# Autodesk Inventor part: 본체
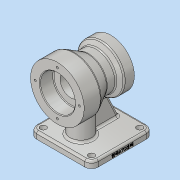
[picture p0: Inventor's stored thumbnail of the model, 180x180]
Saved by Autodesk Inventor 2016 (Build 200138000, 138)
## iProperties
Created: 2019-01
Part Number: 본체
Material: 알루미늄 6061
Document SubType Name: Modeling
Designer: Administrator
Density: 2.7 g/cm^3
Appearance: 알루미늄 - 평지
Mass: 898.816 g
Surface Area: 600.964 cm^2
Volume: 332.895 cm^3
Author: Administrator
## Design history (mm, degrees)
sketch "스케치1"
  geometry: L1 (0, 40)-(25, 40); L2 (25, 40)-(45.785, 28); L3 (45.785, 28)-(59.126, 28); L4 (65, 35)-(80, 35); L5 (80, 35)-(80, 20); L6 (80, 20)-(63, 20); L7 (63, 20)-(63, 16); L8 (63, 16)-(20, 16); L9 (20, 16)-(20, 26); L10 (20, 26)-(0, 26); L11 (0, 26)-(0, 40); L12 (0, 0)-(66.05, 0); L13 (59.126, 28)-(65, 35)
  constraints: 26 end point, 7 perpendicular, 2 horizontal, 2 parallel, 1 vertical alignment
  dimensions: "d0" = 52 diameter of L10 L12; "d1" = 80 diameter of L1 L12; "d2" = 25 distance of L1.start L1.end; "d3" = 80 distance between parallel lines of L5 L11; "d4" = 56 diameter of L3 L12; "d5" = 32 diameter of L8 L12; "d6" = 40 diameter of L6 L12; "d7" = 70 diameter of L4 L12; "d8" = 15 distance of L4.start L4.end; "d9" = 17 distance of L5.end L6.end; "d10" = 20 distance of L9.end L10.end; "d11" = 30 deg angle of L3 L2; "d12" = 50 deg angle of L3 L13
revolve "회전1" sketch "스케치1" stored, may be unused: angle "d13" = 90 deg
node "작업 평면2"
sketch "스케치4"
  geometry: L1 (-46, 5)-(46, 5); L2 (46, 5)-(46, 97); L3 (46, 97)-(-46, 97); L4 (-46, 97)-(-46, 5); L5 (40, 0)-(-40, 0) reference; 3 further points
  constraints: 8 end point, 2 midpoint, 2 parallel, 1 horizontal, 1 perpendicular, 1 vertical alignment
  dimensions: "d19" = 5 distance between parallel lines of L1 L5; "d20" = 92 distance of L1.end L2.end; "d21" = 92 distance of L1.start L1.end
extrude "돌출1" join sketch "스케치4" distance "d22" = 10; taper "d23" = 0 deg
sketch "스케치5"
  geometry: L1 (-46, 5)-(46, 5) reference; L2 (-46, 97)-(-46, 5) reference; C1 r 16 at (0, 35); 1 further point
  constraints: 1 centre point
  dimensions: "d24" = 16 radius of C1; "d25" = 30 distance from line of L1 C1.centre; "d26" = 46 distance from line of C1.centre L2
extrude "돌출2" join sketch "스케치5" stored distance "d27" = 0; taper "d28" = 0 deg
sketch "스케치6"
  geometry: L1 (97, -70)-(5, -70) reference; L2 (87, -70)-(76.94, -48.425); L3 (97, -80)-(97, -70) reference; 1 further point
  constraints: 2 end point, 1 point on line
  dimensions: "d29" = 10 distance of L1.start L2.start; "d30" = 25 deg angle of L3 L2
feature "리브1" sketch "스케치6" dims "d31" = 1, "d32" = 10, "d33" = 0, "d34" = 0, "d35" = 1, "d36" = 1
fillet "모깎기1" dims "d37" = 10
fillet "모깎기2" dims "d38" = 3
sketch "스케치7"
  geometry: L1 (36, 97)-(-36, 97) reference; L2 (46, 15)-(46, 87) reference; L3 (-36, 5)-(36, 5) reference; L4 (-46, 87)-(-46, 15) reference; A1 r 10 centre (-36, 87) between (-36, 97) and (-46, 87) reference; A2 r 10 centre (36, 87) between (46, 87) and (36, 97) reference; A3 r 10 centre (36, 15) between (36, 5) and (46, 15) reference; A4 r 10 centre (-36, 15) between (-46, 15) and (-36, 5) reference; 5 further points
  constraints: 4 coincident
hole "구멍1" sketch "스케치7" at (-36, 87), (36, 87), (36, 15), (-36, 15) diameter "d39" = 9; stored, may be unused: countersink angle "d43" = 90 deg, drill point angle "d45" = 0 deg; dims "d40" = 6, "d41" = 4, "d42" = 2, "d44" = 8
chamfer "모따기1" distance "d46" = 1; stored, may be unused: second distance "d47" = 2, angle "d48" = 45 deg
fillet "모깎기3" dims "d49" = 1
fillet "모깎기4" dims "d50" = 0.6
sketch "스케치8"
  geometry: L1 (0, 0)-(0, 33); 1 further point
  constraints: 2 end point, 1 coincident, 1 vertical
  dimensions: "d51" = 33 distance of L1.start L1.end
hole "구멍2" sketch "스케치8" at (0, 33) diameter "d52" = 3.242; stored, may be unused: countersink angle "d56" = 90 deg, drill point angle "d58" = 118 deg; dims "d53" = 9, "d54" = 4, "d55" = 2, "d57" = 11
sketch "스케치9"
  geometry: L1 (0, 0)-(0, -27.5); 1 further point
  constraints: 2 end point, 1 coincident, 1 vertical
  dimensions: "d62" = 27.5 distance of L1.start L1.end
hole "구멍3" sketch "스케치9" at (0, -27.5) diameter "d63" = 3.242; stored, may be unused: countersink angle "d67" = 90 deg, drill point angle "d69" = 118 deg; dims "d64" = 9, "d65" = 4, "d66" = 2, "d68" = 11
fillet "모깎기5" dims "d73" = 3
fillet "모깎기6" dims "d74" = 3
fillet "모깎기7" dims "d75" = 3
fillet "모깎기8" dims "d76" = 3
sketch "스케치10"
  geometry: L1 (-7, 0)-(-7, 72) reference; L2 (0, 0)-(-7, 0) reference; L3 (0, 0)-(0, 72) reference; L4 (-7, 72)-(0, 72) reference; L5 (-7, -10)-(0, -10) reference; 2 further points
  constraints: 1 other
  dimensions: "d77" = 46 distance from line of L5 point (-4, 36); "d78" = 4 distance from line of L3 point (-4, 36)
feature "엠보싱1" sketch "스케치10" dims "d0" = 52, "d1" = 80, "d2" = 25, "d3" = 80, "d4" = 56, "d5" = 32, "d6" = 40, "d7" = 70, "d8" = 15, "d9" = 17, "d10" = 20, "d11" = 30 deg, "d12" = 50 deg, "d79" = 0.5, "d80" = 0
feature "분할1"
node "솔리드1"
pattern_circular "원형 패턴1" dims angle "d60" = 360 deg
pattern_circular "원형 패턴2" dims angle "d71" = 360 deg
node "투영된 루프1"
node "투영된 루프2"
